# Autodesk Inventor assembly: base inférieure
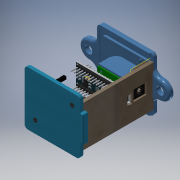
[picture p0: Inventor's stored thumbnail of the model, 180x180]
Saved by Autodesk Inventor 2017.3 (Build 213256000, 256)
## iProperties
Part Number: base inférieure
Material: Générique
Document SubType Name: Assembly
Designer: ficho
Author: ficho
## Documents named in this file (11)
- C:\Users\ficho\Desktop\réforme\activité rentrée\base inférieure.iam
- C:\Users\ficho\Desktop\réforme\activité rentrée\arduino nano.iam
- C:\Users\ficho\Desktop\réforme\activité rentrée\module bluetooth HC05.iam
- C:\Users\ficho\Desktop\réforme\activité rentrée\fiche arduino.ipt
- C:\Users\ficho\Desktop\réforme\activité rentrée\prise DC sur carte.iam
- C:\Users\ficho\Desktop\réforme\activité rentrée\base inférieure.ipt
- C:\Users\ficho\OneDrive\Documents\Inventor\Content Center Files\R2017\fr-FR\ISO 4762(2)\ISO 4762 - M2 x 12ISO.ipt
- C:\Users\ficho\Desktop\réforme\activité rentrée\capot.ipt
- C:\Users\ficho\Desktop\réforme\activité rentrée\capot avant.ipt
- C:\Users\ficho\Desktop\réforme\activité rentrée\bouchon.ipt
- C:\Users\ficho\OneDrive\Documents\Inventor\Content Center Files\R2017\fr-FR\ISO 7046-2 H\ISO 7046-2 H - M2x12 - 8.8 - H1.ipt
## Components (13 placed, 10 different names)
1. arduino nano:1 [sub-assembly] — Placage:1, Placage:2, Placage:5, Affleurement:1, Affleurement:2, Placage:6, Placage:7, Placage:8
2. module bluetooth HC05:1 [sub-assembly] — Placage:3, Placage:4, Placage:5, Affleurement:1, Affleurement:2
3. fiche arduino:7 — Placage:1, Placage:2
4. fiche arduino:8 — Placage:3, Placage:4
5. prise DC sur carte:1 [sub-assembly] — Placage:6, Placage:7, Placage:8, Affleurement:3
6. base inférieure:1 — Affleurement:3, Placage:9, Placage:10, Placage:11, Affleurement:4, Affleurement:5
7. ISO 4762 M2 x 12:1
8. ISO 4762 M2 x 12:2
9. capot:1 — Placage:9, Placage:10, Placage:11, Affleurement:6, Affleurement:7
10. capot avant:1 — Affleurement:4, Affleurement:5
11. bouchon:1 — Affleurement:6, Affleurement:7
12. ISO 7046-2 H M2x12 - 8.8 - H1:1
13. ISO 7046-2 H M2x12 - 8.8 - H1:2
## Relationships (18: Mate 11, Flush 7)
- Placage:1 [Mate]: arduino nano:1 ↔ fiche arduino:7
- Placage:2 [Mate]: arduino nano:1 ↔ fiche arduino:7
- Placage:3 [Mate]: module bluetooth HC05:1 ↔ fiche arduino:8
- Placage:4 [Mate]: module bluetooth HC05:1 ↔ fiche arduino:8
- Placage:5 [Mate]: arduino nano:1 ↔ module bluetooth HC05:1
- Affleurement:1 [Flush]: arduino nano:1 ↔ module bluetooth HC05:1
- Affleurement:2 [Flush]: arduino nano:1 ↔ module bluetooth HC05:1
- Placage:6 [Mate]: arduino nano:1 ↔ prise DC sur carte:1
- Placage:7 [Mate]: arduino nano:1 ↔ prise DC sur carte:1
- Placage:8 [Mate]: arduino nano:1 ↔ prise DC sur carte:1
- Affleurement:3 [Flush]: prise DC sur carte:1 ↔ base inférieure:1
- Placage:9 [Mate]: base inférieure:1 ↔ capot:1
- Placage:10 [Mate]: base inférieure:1 ↔ capot:1
- Placage:11 [Mate]: base inférieure:1 ↔ capot:1
- Affleurement:4 [Flush]: base inférieure:1 ↔ capot avant:1
- Affleurement:5 [Flush]: base inférieure:1 ↔ capot avant:1
- Affleurement:6 [Flush]: capot:1 ↔ bouchon:1
- Affleurement:7 [Flush]: capot:1 ↔ bouchon:1
